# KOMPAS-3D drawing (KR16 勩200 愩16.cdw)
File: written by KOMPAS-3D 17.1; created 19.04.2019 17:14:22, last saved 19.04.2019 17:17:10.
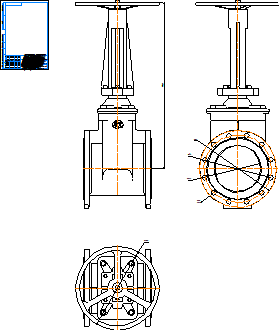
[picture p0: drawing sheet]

Sheet 1: A4, portrait

Title block, sheet 1: name: KR16 Ду200 Ру16; material: Внимание! Данный продукт является объектом авторского права ООО «Торговый Дом АДЛ». / Запрещается изменение, копирование, распространение / (в том числе путем копирования на другие сайты и ресурсы в Интернете) / или любое иное использование информации и объектов без предварительного / согласия правообладателя (ООО «Торговый Дом АДЛ»).; mass: 142,14; sheets: 1; organisation: ООО "Торговый дом АДЛ"; sheet format: A4

Views: Вид 1, Проекционный вид 2, Проекционный вид 3
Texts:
  user
Dimensions and other numbers on the sheet: 722,46; 200; 22; 12 Отв.; 335; 295; 363,2; 1:1; 1; 142,14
